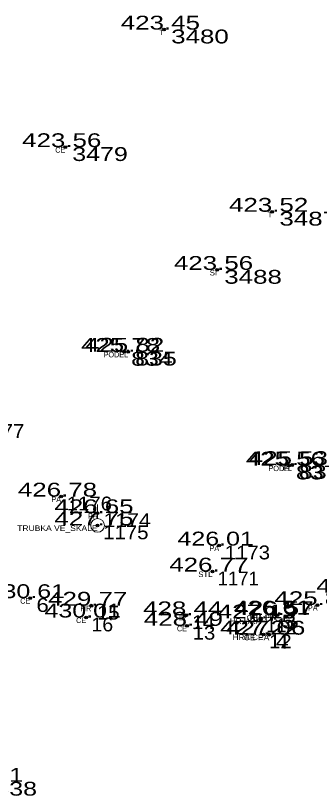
# Model space of a CAD drawing. Extents: x -639390 to -639074, y -1138747 to -1138358.
# Drawn here: x -639174.44 to -639157.96, y -1138659.59 to -1138617.56 of the extents above; entities that cross this region are included whole.
import ezdxf
from ezdxf.enums import TextEntityAlignment as Align

# ---------------------------------------------------------------- set-up
doc = ezdxf.new("R2010")
doc.units = 0
doc.header["$LTSCALE"] = 0.3
doc.header["$PDMODE"] = 32
doc.header["$PDSIZE"] = 0.15
for name, color, linetype in [('11', 7, 'Continuous'), ('12', 7, 'Continuous'), ('13', 7, 'Continuous'), ('57', 7, 'Continuous')]:
    doc.layers.add(name, color=color, linetype=linetype)
doc.layers.add('21', color=7, linetype='Continuous', lineweight=13)

msp = doc.modelspace()

# ---------------------------------------------------------------- linework, layer by layer
at = {"layer": '11'}
for p in [(-639166.39, -1138618.32), (-639171.74, -1138624.69), (-639160.52, -1138628.19), (-639163.51, -1138631.34), (-639168.55, -1138635.78), (-639168.33, -1138635.77), (-639159.61, -1138641.94), (-639159.45, -1138641.91), (-639171.97, -1138643.62), (-639169.99, -1138644.52), (-639169.99, -1138645.18), (-639163.4, -1138646.27), (-639163.76, -1138647.68), (-639173.64, -1138649.12), (-639158.06, -1138649.5), (-639170.33, -1138649.53), (-639170.61, -1138650.17), (-639165.18, -1138650.05), (-639161.13, -1138650.22), (-639160.34, -1138650.01), (-639160.23, -1138650.04), (-639165.14, -1138650.62), (-639161, -1138651.09), (-639160.68, -1138651.1)]:
    msp.add_point(p, dxfattribs=at)
at = {"layer": '21'}
msp.add_line((-639169.99, -1138644.805), (-639169.99, -1138644.055), dxfattribs=at)
for radius in [0.375, 0.05]:
    msp.add_circle((-639169.99, -1138645.18), radius, dxfattribs=at)

# ---------------------------------------------------------------- texts
at = {"layer": '12'}
for s, width, p in [('423.45 ', 1.4, (-639166.39, -1138618.32)), ('423.56 ', 1.4, (-639171.739, -1138624.69)), ('423.52 ', 1.4, (-639160.52, -1138628.19)), ('423.56 ', 1.4, (-639163.509, -1138631.34)), ('425.78 ', 1.4, (-639168.55, -1138635.78)), ('425.82 ', 1.4, (-639168.33, -1138635.77)), ('425.56 ', 1.4, (-639159.609, -1138641.94)), ('425.53 ', 1.4, (-639159.45, -1138641.91)), ('426.78 ', 1.4, (-639171.97, -1138643.62)), ('426.65 ', 1.4, (-639169.99, -1138644.52)), ('427.75 ', 1.4, (-639169.99, -1138645.18)), ('426.01 ', 1.35, (-639163.399, -1138646.27)), ('426.77 ', 1.4, (-639163.76, -1138647.68)), ('425.38 ', 1.4, (-639155.79, -1138648.83)), ('430.61 ', 1.35, (-639173.639, -1138649.12)), ('429.77 ', 1.4, (-639170.33, -1138649.53)), ('425.83 ', 1.4, (-639158.06, -1138649.5)), ('430.01 ', 1.35, (-639170.609, -1138650.17)), ('428.44 ', 1.4, (-639165.18, -1138650.05)), ('426.61 ', 1.35, (-639160.339, -1138650.01)), ('426.57 ', 1.4, (-639160.23, -1138650.04)), ('428.49 ', 1.4, (-639165.14, -1138650.62)), ('427.19 ', 1.4, (-639161.13, -1138650.22)), ('427.22 ', 1.4, (-639161, -1138651.09)), ('427.06 ', 1.4, (-639160.679, -1138651.1)), ('438.31 ', 1.35, (-639175.909, -1138659.07))]:
    msp.add_text(s, height=0.75, dxfattribs=dict(at, width=width)).set_placement(p, align=Align.CENTER)
at = {"layer": '13'}
for s, width, p in [(' 3480', 1.4, (-639166.39, -1138619.07)), (' 3479', 1.35, (-639171.74, -1138625.44)), (' 3487', 1.4, (-639160.52, -1138628.94)), (' 3488', 1.4, (-639163.51, -1138632.09)), (' 834', 1.35, (-639168.55, -1138636.53)), (' 835', 1.35, (-639168.33, -1138636.52)), (' 1177', 1.1, (-639176.72, -1138640.44)), (' 837', 1.35, (-639159.61, -1138642.69)), (' 836', 1.35, (-639159.45, -1138642.66)), (' 1176', 1.1, (-639171.97, -1138644.37)), (' 1174', 1.15, (-639169.99, -1138645.27)), (' 1175', 1.1, (-639169.99, -1138645.93)), (' 1173', 1.1, (-639163.4, -1138647.02)), (' 6', 1.2, (-639173.64, -1138649.87)), (' 15', 1.1, (-639170.33, -1138650.28)), (' 16', 1.05, (-639170.61, -1138650.92)), (' 14', 1.1, (-639165.18, -1138650.8)), (' 5', 1.2, (-639160.34, -1138650.76)), (' 3', 1.2, (-639160.23, -1138650.79)), (' 13', 1.1, (-639165.14, -1138651.37)), (' 12', 1.1, (-639161, -1138651.84)), (' 4', 1.25, (-639160.68, -1138651.85)), (' 538', 1.35, (-639175.91, -1138659.82))]:
    msp.add_text(s, height=0.75, dxfattribs=dict(at, width=width)).set_placement(p)
for s, p in [(' 1171', (-639163.76, -1138648.43)), (' 11', (-639161.13, -1138650.97))]:
    msp.add_text(s, height=0.75, dxfattribs=at).set_placement(p)
at = {"layer": '57'}
for s, width, p in [('T', 0.85, (-639166.39, -1138618.62)), ('CE', 0.9, (-639171.74, -1138624.99)), ('T', 0.85, (-639160.52, -1138628.49)), ('SI', 1.05, (-639163.51, -1138631.64)), ('PODE', 0.95, (-639168.55, -1138636.08)), ('PODE', 0.95, (-639159.61, -1138642.24)), ('PA', 0.95, (-639171.97, -1138643.92)), ('PA', 0.95, (-639169.99, -1138644.82)), ('TRUBKA VE_SKALE', 1.15, (-639169.99, -1138645.48)), ('PA', 0.95, (-639163.4, -1138646.57)), ('STL', 1.05, (-639163.759, -1138647.98)), ('CE', 0.9, (-639173.64, -1138649.42)), ('HR', 0.85, (-639170.329, -1138649.83)), ('PA', 0.95, (-639158.06, -1138649.8)), ('CE', 0.9, (-639170.61, -1138650.47)), ('HR', 0.85, (-639165.179, -1138650.35)), ('HR HRA', 1.1, (-639161.13, -1138650.52)), ('CEL HR', 1.15, (-639160.229, -1138650.34)), ('HR PA', 1.15, (-639160.34, -1138650.31)), ('CE', 0.9, (-639165.14, -1138650.92)), ('HRA CE', 1.1, (-639161, -1138651.39)), ('CE PA', 1.15, (-639160.68, -1138651.4))]:
    msp.add_text(s, height=0.3, dxfattribs=dict(at, width=width)).set_placement(p, align=Align.RIGHT)
for p in [(-639168.329, -1138636.07), (-639159.449, -1138642.21)]:
    msp.add_text('PL', height=0.3, dxfattribs=at).set_placement(p, align=Align.RIGHT)

doc.saveas('drawing.dxf')
